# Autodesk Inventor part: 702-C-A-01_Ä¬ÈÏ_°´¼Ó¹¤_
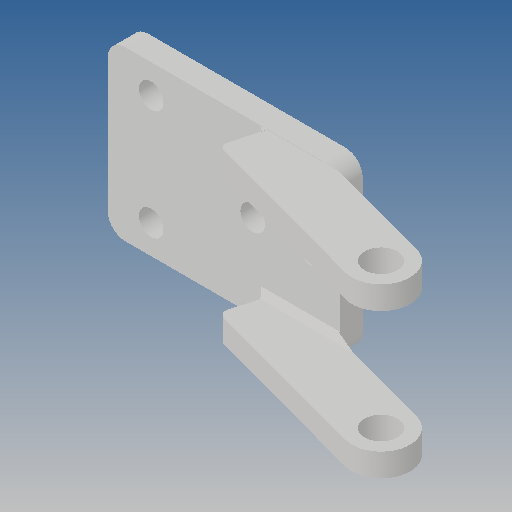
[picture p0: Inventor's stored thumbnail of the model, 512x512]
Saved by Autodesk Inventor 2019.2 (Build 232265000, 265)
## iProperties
Created: 2010-06
Part Number: 702-C-A-01_Ä¬ÈÏ_°´¼Ó¹¤_
Material: Ogólny
Document SubType Name: Modeling
Designer: CADENGINEERING4
Density: 1 g/cm^3
Appearance: Domyślna
Author: CADENGINEERING4
Revision Number: ÈÎºÎ
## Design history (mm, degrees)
feature "NONE"
feature "NONE:1"
feature "NONE:2"
feature "NONE:3"
feature "NONE:4"
node "Bryła1"
node "Bryła2"
node "Bryła3"
node "Bryła4"
node "Bryła5"
